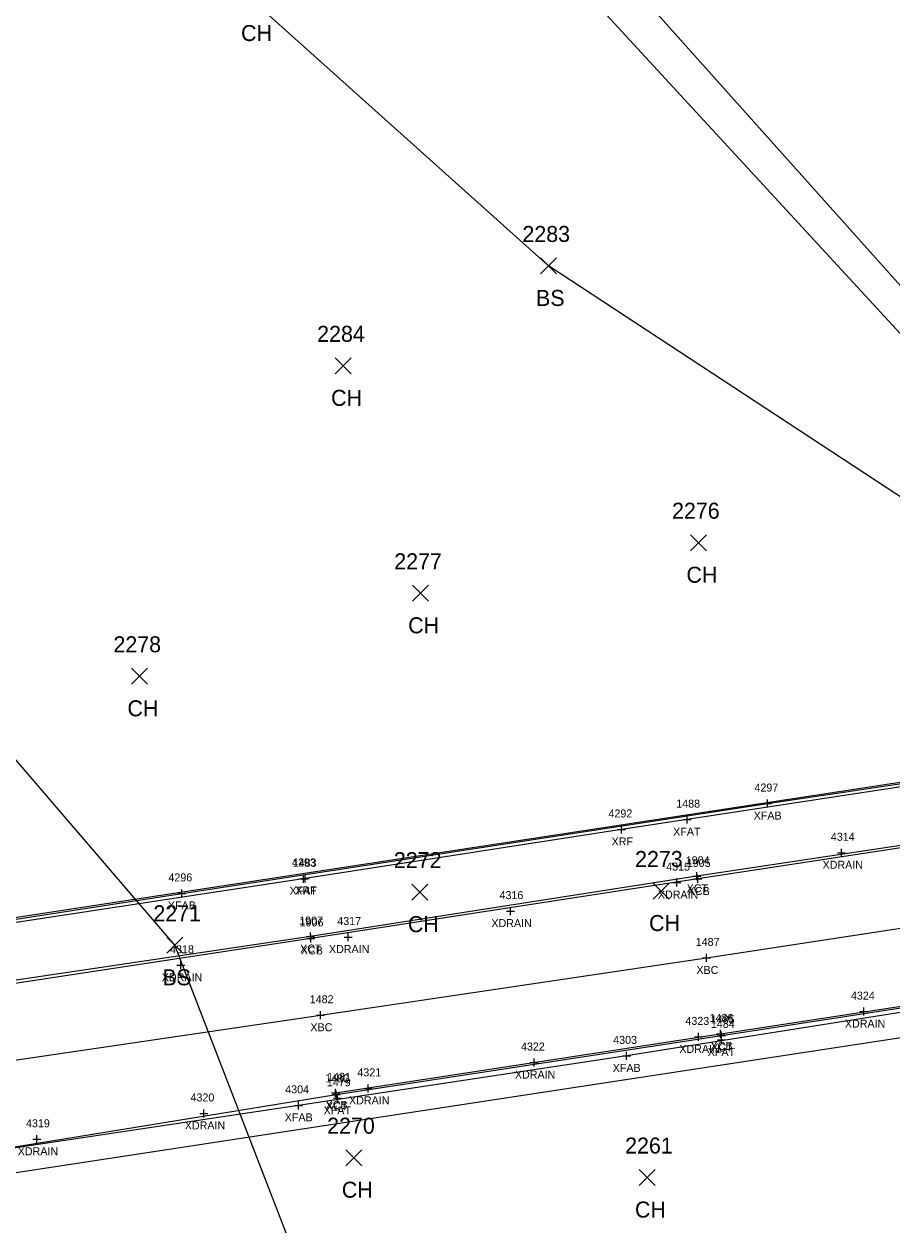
# Model space of a CAD drawing. Extents: x 1509053 to 1511576, y 400838 to 402572.
# Drawn here: x 1509874.8 to 1509983.2, y 401587.4 to 401737.4 of the extents above; entities that cross this region are included whole.
import ezdxf

# ---------------------------------------------------------------- set-up
doc = ezdxf.new("R2010")
doc.units = 0
for name, color, linetype in [('B_A', 7, 'Continuous'), ('B_I', 7, 'Continuous'), ('B_TIC', 7, 'Continuous'), ('BDC', 7, 'Continuous'), ('BELB', 7, 'Continuous'), ('BF', 7, 'Continuous'), ('BR', 7, 'Continuous'), ('DCP', 7, 'Continuous'), ('L_A', 7, 'Continuous'), ('L_I', 7, 'Continuous'), ('L_TIC', 7, 'Continuous'), ('LAWE', 7, 'Continuous'), ('LELB', 7, 'Continuous')]:
    doc.layers.add(name, color=color, linetype=linetype)

msp = doc.modelspace()

# ---------------------------------------------------------------- linework, layer by layer
at = {"layer": 'B_TIC'}
for p, q in [((1509967.63, 401640.04), (1509967.71, 401640.04)), ((1509957.58, 401638.03), (1509957.66, 401638.03)), ((1509949.39, 401636.8), (1509949.47, 401636.8)), ((1509976.89, 401633.89), (1509976.97, 401633.89)), ((1509909.66, 401630.64), (1509909.74, 401630.64)), ((1509909.86, 401630.68), (1509909.94, 401630.68)), ((1509958.81, 401630.95), (1509958.88, 401630.95)), ((1509958.93, 401630.62), (1509959.01, 401630.62)), ((1509894.45, 401628.81), (1509894.53, 401628.81)), ((1509956.32, 401630.16), (1509956.4, 401630.16)), ((1509935.52, 401626.6), (1509935.6, 401626.6)), ((1509910.52, 401623.42), (1509910.6, 401623.42)), ((1509910.6, 401623.19), (1509910.67, 401623.19)), ((1509915.23, 401623.36), (1509915.31, 401623.36)), ((1509894.35, 401619.83), (1509894.43, 401619.83)), ((1509960.01, 401620.75), (1509960.09, 401620.75)), ((1509979.68, 401614.04), (1509979.76, 401614.04)), ((1509911.79, 401613.59), (1509911.86, 401613.59)), ((1509959, 401610.88), (1509959.08, 401610.88)), ((1509961.77, 401611.26), (1509961.85, 401611.26)), ((1509961.89, 401611.06), (1509961.96, 401611.06)), ((1509961.9, 401610.51), (1509961.98, 401610.51)), ((1509950.02, 401608.51), (1509950.1, 401608.51)), ((1509938.46, 401607.68), (1509938.54, 401607.68)), ((1509913.69, 401603.89), (1509913.76, 401603.89)), ((1509913.76, 401603.7), (1509913.84, 401603.7)), ((1509917.74, 401604.45), (1509917.82, 401604.45)), ((1509909.05, 401602.33), (1509909.13, 401602.33)), ((1509913.93, 401603.21), (1509914, 401603.21)), ((1509897.22, 401601.32), (1509897.3, 401601.32)), ((1509876.35, 401598.09), (1509876.43, 401598.09))]:
    msp.add_line(p, q, dxfattribs=at)
for points in [[(1509967.13, 401640.04), (1509968.13, 401640.04)], [(1509967.63, 401639.54), (1509967.63, 401640.54)], [(1509957.08, 401638.03), (1509958.08, 401638.03)], [(1509957.58, 401637.53), (1509957.58, 401638.53)], [(1509948.89, 401636.8), (1509949.89, 401636.8)], [(1509949.39, 401636.3), (1509949.39, 401637.3)], [(1509976.39, 401633.89), (1509977.39, 401633.89)], [(1509976.89, 401633.39), (1509976.89, 401634.39)], [(1509909.16, 401630.64), (1509910.16, 401630.64)], [(1509909.36, 401630.68), (1509910.36, 401630.68)], [(1509909.66, 401630.13), (1509909.66, 401631.14)], [(1509909.86, 401630.18), (1509909.86, 401631.18)], [(1509956.32, 401629.66), (1509956.32, 401630.66)], [(1509958.31, 401630.95), (1509959.31, 401630.95)], [(1509958.43, 401630.62), (1509959.43, 401630.62)], [(1509958.81, 401630.45), (1509958.81, 401631.45)], [(1509958.93, 401630.12), (1509958.93, 401631.12)], [(1509893.95, 401628.81), (1509894.95, 401628.81)], [(1509894.45, 401628.31), (1509894.45, 401629.31)], [(1509955.82, 401630.16), (1509956.82, 401630.16)], [(1509935.02, 401626.6), (1509936.02, 401626.6)], [(1509935.52, 401626.1), (1509935.52, 401627.1)], [(1509910.02, 401623.42), (1509911.02, 401623.42)], [(1509910.09, 401623.19), (1509911.09, 401623.19)], [(1509910.52, 401622.92), (1509910.52, 401623.93)], [(1509910.59, 401622.69), (1509910.59, 401623.69)], [(1509914.73, 401623.36), (1509915.73, 401623.36)], [(1509915.23, 401622.86), (1509915.23, 401623.86)], [(1509893.85, 401619.83), (1509894.85, 401619.83)], [(1509894.35, 401619.33), (1509894.35, 401620.33)], [(1509959.51, 401620.75), (1509960.51, 401620.75)], [(1509960.01, 401620.25), (1509960.01, 401621.25)], [(1509911.78, 401613.09), (1509911.78, 401614.09)], [(1509979.18, 401614.04), (1509980.18, 401614.04)], [(1509979.68, 401613.54), (1509979.68, 401614.54)], [(1509911.28, 401613.59), (1509912.28, 401613.59)], [(1509958.5, 401610.88), (1509959.5, 401610.88)], [(1509959, 401610.38), (1509959, 401611.38)], [(1509961.27, 401611.26), (1509962.27, 401611.26)], [(1509961.38, 401611.06), (1509962.38, 401611.06)], [(1509961.77, 401610.76), (1509961.77, 401611.76)], [(1509961.88, 401610.56), (1509961.88, 401611.56)], [(1509961.9, 401610.01), (1509961.9, 401611.01)], [(1509961.4, 401610.51), (1509962.4, 401610.51)], [(1509938.46, 401607.18), (1509938.46, 401608.18)], [(1509949.52, 401608.51), (1509950.52, 401608.51)], [(1509950.02, 401608.01), (1509950.02, 401609.01)], [(1509937.96, 401607.68), (1509938.96, 401607.68)], [(1509917.74, 401603.95), (1509917.74, 401604.95)], [(1509913.18, 401603.89), (1509914.18, 401603.89)], [(1509913.26, 401603.7), (1509914.26, 401603.7)], [(1509913.68, 401603.39), (1509913.68, 401604.39)], [(1509913.76, 401603.2), (1509913.76, 401604.2)], [(1509913.93, 401602.71), (1509913.93, 401603.71)], [(1509917.24, 401604.45), (1509918.24, 401604.45)], [(1509897.22, 401600.82), (1509897.22, 401601.82)], [(1509908.55, 401602.33), (1509909.55, 401602.33)], [(1509909.05, 401601.83), (1509909.05, 401602.83)], [(1509913.43, 401603.21), (1509914.43, 401603.21)], [(1509896.72, 401601.32), (1509897.72, 401601.32)], [(1509875.85, 401598.09), (1509876.85, 401598.09)], [(1509876.35, 401597.59), (1509876.35, 401598.59)]]:
    msp.add_lwpolyline(points, dxfattribs=at)
at = {"layer": 'BDC'}
for points in [[(1510006.15, 401638.09), (1509958.81, 401630.95), (1509910.52, 401623.42)], [(1510006.13, 401637.85), (1509958.93, 401630.62), (1509910.59, 401623.19)], [(1509865.36, 401595.82), (1509913.76, 401603.7), (1509961.88, 401611.06), (1510009.41, 401618.39), (1510057.04, 401625.49), (1510072.28, 401627.78)], [(1509913.68, 401603.89), (1509961.77, 401611.26), (1510009.34, 401618.55), (1510057, 401625.64), (1510072.41, 401628.04)], [(1509910.52, 401623.42), (1509861.66, 401616.19)], [(1509910.59, 401623.19), (1509861.83, 401615.77)]]:
    msp.add_lwpolyline(points, dxfattribs=at)
at = {"layer": 'BELB'}
msp.add_lwpolyline([(1509863.37, 401606.46), (1509911.78, 401613.59), (1509960.01, 401620.75), (1510007.43, 401628.03), (1510070.82, 401637.95), (1510054.85, 401635.39)], dxfattribs=at)
at = {"layer": 'BF'}
for points in [[(1509861.08, 401623.62), (1509894.45, 401628.81), (1509967.63, 401640.04), (1510017.64, 401647.51), (1510068.15, 401655.21)], [(1510071.84, 401626.31), (1510032.23, 401621.12), (1509992.39, 401615.24), (1509950.02, 401608.51), (1509909.05, 401602.33), (1509865.36, 401595.79)]]:
    msp.add_lwpolyline(points, dxfattribs=at)
at = {"layer": 'BR'}
msp.add_lwpolyline([(1510068.57, 401654.77), (1510050.77, 401652.06), (1510019.36, 401647.26), (1509987.32, 401642.58), (1509949.39, 401636.8), (1509909.86, 401630.68), (1509861.46, 401623.31)], dxfattribs=at)
at = {"layer": 'DCP'}
for points in [[(1509855.59, 401623.04), (1510068.37, 401655.58)], [(1509865.54, 401592.71), (1510072.48, 401624.26)]]:
    msp.add_lwpolyline(points, dxfattribs=at)
at = {"layer": 'L_TIC'}
for points in [[(1509939.27, 401706.21), (1509941.27, 401708.21)], [(1509941.27, 401706.21), (1509939.27, 401708.21)], [(1509913.63, 401693.73), (1509915.63, 401695.73)], [(1509915.63, 401693.73), (1509913.63, 401695.73)], [(1509958.02, 401671.63), (1509960.02, 401673.63)], [(1509960.02, 401671.63), (1509958.02, 401673.63)], [(1509923.26, 401665.31), (1509925.26, 401667.31)], [(1509925.26, 401665.31), (1509923.26, 401667.31)], [(1509888.18, 401654.94), (1509890.18, 401656.94)], [(1509890.18, 401654.94), (1509888.18, 401656.94)], [(1509923.21, 401627.97), (1509925.21, 401629.97)], [(1509925.21, 401627.97), (1509923.21, 401629.97)], [(1509953.34, 401628.11), (1509955.34, 401630.11)], [(1509955.34, 401628.11), (1509953.34, 401630.11)], [(1509892.6, 401621.33), (1509894.6, 401623.33)], [(1509894.6, 401621.33), (1509892.6, 401623.33)], [(1509914.97, 401594.79), (1509916.97, 401596.79)], [(1509916.97, 401594.79), (1509914.97, 401596.79)], [(1509951.58, 401592.31), (1509953.58, 401594.31)], [(1509953.58, 401592.31), (1509951.58, 401594.31)]]:
    msp.add_lwpolyline(points, dxfattribs=at)
at = {"layer": 'LAWE'}
msp.add_lwpolyline([(1509999.39, 401682.29), (1509931.32, 401756.22), (1509918.51, 401791.76)], dxfattribs=at)
at = {"layer": 'LELB'}
for points in [[(1510002.64, 401684.14), (1509936.25, 401758.43)], [(1509940.27, 401707.21), (1509903.37, 401740.31)], [(1510431.72, 401516.61), (1510341.14, 401547.81), (1510292.56, 401583.77), (1510226.42, 401599.28), (1510151.75, 401587.72), (1510095.68, 401580.81), (1510017.56, 401603.54), (1510015.48, 401644.92), (1509989.35, 401675.01), (1509940.27, 401707.21)], [(1510375.28, 401447.94), (1510312.66, 401505.77), (1510258.93, 401525.17), (1510195.12, 401538.28), (1510140.28, 401539.55), (1510091.11, 401540.23), (1510018.72, 401547.48), (1509966.51, 401548.78), (1509913.37, 401571.2), (1509893.6, 401622.33), (1509860.64, 401660.7)]]:
    msp.add_lwpolyline(points, dxfattribs=at)

# ---------------------------------------------------------------- texts
at = {"layer": 'B_A'}
for s, p in [('XFAB', (1509965.9, 401638.04)), ('XFAT', (1509955.84, 401636.03)), ('XRF', (1509948.15, 401634.8)), ('XDRAIN', (1509974.5, 401631.89)), ('XFAT', (1509907.92, 401628.64)), ('XRF', (1509908.62, 401628.68)), ('XDRAIN', (1509953.93, 401628.16)), ('XCT', (1509957.53, 401628.95)), ('XCB', (1509957.66, 401628.62)), ('XFAB', (1509892.72, 401626.81)), ('XDRAIN', (1509933.13, 401624.6)), ('XCT', (1509909.24, 401621.42)), ('XCB', (1509909.33, 401621.19)), ('XDRAIN', (1509912.84, 401621.36)), ('XDRAIN', (1509891.96, 401617.83)), ('XBC', (1509958.74, 401618.75)), ('XBC', (1509910.52, 401611.59)), ('XDRAIN', (1509977.29, 401612.04)), ('XDRAIN', (1509956.61, 401608.88)), ('XFAT', (1509960.16, 401608.51)), ('XCB', (1509960.5, 401609.26)), ('XCT', (1509960.6, 401609.06)), ('XDRAIN', (1509936.07, 401605.68)), ('XFAB', (1509948.29, 401606.51)), ('XDRAIN', (1509915.35, 401602.45)), ('XFAT', (1509912.18, 401601.21)), ('XCB', (1509912.42, 401601.89)), ('XCT', (1509912.48, 401601.7)), ('XDRAIN', (1509894.83, 401599.32)), ('XFAB', (1509907.32, 401600.33)), ('XDRAIN', (1509873.96, 401596.09))]:
    msp.add_text(s, height=1, dxfattribs=at).set_placement(p)
at = {"layer": 'B_I'}
for s, p in [('4297', (1509966, 401641.54)), ('4292', (1509947.76, 401638.3)), ('1488', (1509956.23, 401639.53)), ('4314', (1509975.54, 401635.39)), ('1904', (1509957.42, 401632.45)), ('4293', (1509908.23, 401632.18)), ('1483', (1509908.31, 401632.14)), ('4315', (1509954.97, 401631.66)), ('1905', (1509957.54, 401632.12)), ('4296', (1509892.79, 401630.31)), ('4316', (1509934.15, 401628.1)), ('1907', (1509909.13, 401624.92)), ('4317', (1509913.88, 401624.86)), ('1906', (1509909.18, 401624.69)), ('1487', (1509958.66, 401622.25)), ('4318', (1509893, 401621.33)), ('1482', (1509910.44, 401615.09)), ('4324', (1509978.05, 401615.54)), ('4323', (1509957.37, 401612.38)), ('1486', (1509960.39, 401612.76)), ('1485', (1509960.54, 401612.56)), ('1484', (1509960.55, 401612.01)), ('4303', (1509948.35, 401610.01)), ('4322', (1509936.83, 401609.18)), ('1481', (1509912.62, 401605.39)), ('4321', (1509916.39, 401605.95)), ('4304', (1509907.38, 401603.83)), ('1480', (1509912.37, 401605.2)), ('1479', (1509912.58, 401604.71)), ('4320', (1509895.55, 401602.82)), ('4319', (1509875, 401599.59))]:
    msp.add_text(s, height=1, dxfattribs=at).set_placement(p)
at = {"layer": 'L_A'}
for s, p in [('CH', (1509901.86, 401735.31)), ('BS', (1509938.71, 401702.21)), ('CH', (1509913.11, 401689.73)), ('CH', (1509957.5, 401667.63)), ('CH', (1509922.74, 401661.31)), ('CH', (1509887.67, 401650.94)), ('CH', (1509922.7, 401623.97)), ('CH', (1509952.83, 401624.11)), ('BS', (1509892.04, 401617.33)), ('CH', (1509914.45, 401590.79)), ('CH', (1509951.07, 401588.31))]:
    msp.add_text(s, height=2, dxfattribs=at).set_placement(p)
at = {"layer": 'L_I'}
for s, p in [('2283', (1509937.01, 401710.21)), ('2284', (1509911.37, 401697.73)), ('2276', (1509955.7, 401675.63)), ('2277', (1509921, 401669.31)), ('2278', (1509885.92, 401658.94)), ('2272', (1509920.95, 401631.97)), ('2273', (1509951.08, 401632.11)), ('2271', (1509890.91, 401625.33)), ('2270', (1509912.62, 401598.79)), ('2261', (1509949.84, 401596.31))]:
    msp.add_text(s, height=2, dxfattribs=at).set_placement(p)

doc.saveas('drawing.dxf')
